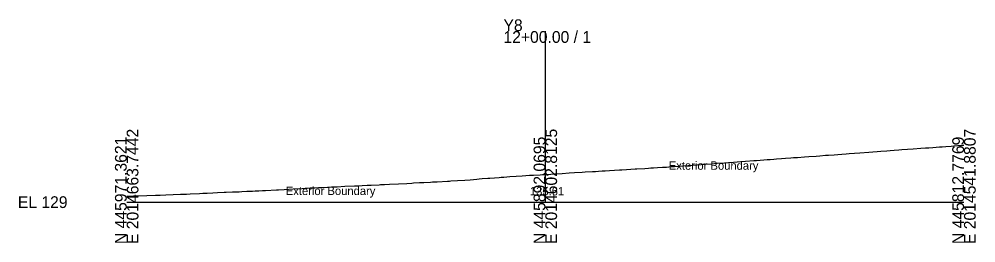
# Model space of a CAD drawing. Extents: x -26 to 1403, y -10 to 8043.
# Drawn here: x -25.7 to 202.8, y 3990.3 to 4043.6 of the extents above; entities that cross this region are included whole.
import ezdxf

# ---------------------------------------------------------------- set-up
doc = ezdxf.new("R2010")
doc.units = 0
for name, color, linetype in [('Default', 7, 'Continuous'), ('Exist Cross Section Cell', 7, 'Continuous'), ('Exist XS Center Line Elevation Label', 7, 'Continuous'), ('Exist XS Ground Line', 7, 'Continuous'), ('Scratch_Level_0', 7, 'Continuous')]:
    doc.layers.add(name, color=color, linetype=linetype)

msp = doc.modelspace()

# ---------------------------------------------------------------- linework, layer by layer
at = {"layer": 'Exist Cross Section Cell'}
for p, q in [((100, 4000), (100, 4040.76)), ((0, 4000), (100, 4000)), ((100, 4000), (200, 4000))]:
    msp.add_line(p, q, dxfattribs=at)
at = {"layer": 'Exist XS Ground Line'}
msp.add_lwpolyline([(0, 4001.44), (0.53, 4001.46), (1.66, 4001.49), (2.83, 4001.52), (4.78, 4001.58), (6.92, 4001.66), (7.98, 4001.69), (9.32, 4001.74), (11.09, 4001.81), (12.86, 4001.87), (14.27, 4001.94), (15.14, 4001.98), (17.41, 4002.08), (18.21, 4002.12), (19.24, 4002.17), (20.58, 4002.23), (21.72, 4002.28), (23.31, 4002.35), (23.78, 4002.37), (25.31, 4002.42), (26.87, 4002.49), (27.53, 4002.52), (28.68, 4002.58), (29.36, 4002.61), (30.04, 4002.64), (30.69, 4002.67), (31.57, 4002.72), (32.47, 4002.75), (33.13, 4002.78), (35.82, 4002.93), (36.29, 4002.95), (37.62, 4003), (39.75, 4003.16), (41.88, 4003.26), (42.62, 4003.32), (43.12, 4003.34), (43.79, 4003.38), (44.94, 4003.43), (45.78, 4003.47), (46.72, 4003.5), (47.94, 4003.58), (48.26, 4003.59), (48.95, 4003.63), (50.28, 4003.67), (52.12, 4003.79), (54.41, 4003.86), (55.26, 4003.91), (56.21, 4003.96), (57.42, 4004.01), (58.42, 4004.06), (60.29, 4004.16), (60.66, 4004.17), (61.56, 4004.21), (62.77, 4004.25), (64.9, 4004.39), (66.91, 4004.47), (68.12, 4004.55), (68.48, 4004.57), (69.93, 4004.65), (71, 4004.71), (72.56, 4004.78), (73.08, 4004.81), (74.15, 4004.86), (76.61, 4005.01), (77.07, 4005.03), (77.45, 4005.05), (79.03, 4005.13), (80.77, 4005.27), (82.03, 4005.35), (83.66, 4005.5), (84.18, 4005.54), (84.9, 4005.6), (86.27, 4005.71), (86.76, 4005.75), (88.97, 4005.91), (89.43, 4005.94), (90.1, 4005.99), (91.55, 4006.08), (93.06, 4006.19), (94.47, 4006.27), (96.2, 4006.39), (97.16, 4006.45), (98.75, 4006.54), (99.36, 4006.58), (100.2, 4006.62), (101.3, 4006.7), (101.87, 4006.73), (102.72, 4006.78), (104, 4006.85), (105.67, 4006.97), (106.93, 4007.04), (108.82, 4007.16), (109.54, 4007.21), (111.26, 4007.29), (111.97, 4007.34), (112.69, 4007.38), (113.61, 4007.44), (114.33, 4007.48), (115.32, 4007.54), (116.49, 4007.59), (117.68, 4007.68), (118.29, 4007.71), (119.35, 4007.76), (121.47, 4007.91), (121.87, 4007.93), (123.77, 4008.03), (124.65, 4008.1), (125.19, 4008.14), (125.85, 4008.18), (126.77, 4008.23), (127.98, 4008.31), (128.97, 4008.37), (130.08, 4008.46), (130.83, 4008.51), (131.81, 4008.58), (134.12, 4008.76), (136.27, 4008.9), (137.24, 4008.98), (137.65, 4009.02), (138.15, 4009.05), (139.73, 4009.16), (141.08, 4009.25), (142.79, 4009.38), (143.73, 4009.45), (144.92, 4009.54), (146.67, 4009.68), (147.79, 4009.75), (149.83, 4009.91), (150.47, 4009.96), (152.22, 4010.07), (152.99, 4010.13), (153.67, 4010.18), (154.57, 4010.25), (155.22, 4010.3), (156.41, 4010.38), (157.39, 4010.46), (158.68, 4010.55), (159.24, 4010.6), (160.21, 4010.67), (161.93, 4010.79), (162.93, 4010.86), (164.73, 4010.99), (165.59, 4011.06), (166.91, 4011.16), (167.64, 4011.21), (169.02, 4011.31), (169.85, 4011.37), (170.85, 4011.45), (171.85, 4011.52), (172.61, 4011.58), (175.12, 4011.77), (177.24, 4011.93), (178.2, 4012), (179.28, 4012.08), (180.13, 4012.15), (181.6, 4012.25), (182.37, 4012.31), (183.35, 4012.38), (184.4, 4012.45), (185.13, 4012.51), (187.83, 4012.7), (189.73, 4012.84), (190.83, 4012.92), (191.63, 4012.97), (192.59, 4013.05), (194.14, 4013.16), (194.83, 4013.21), (195.69, 4013.27), (196.93, 4013.36), (197.58, 4013.41), (199.42, 4013.54), (200, 4013.59)], dxfattribs=at)

# ---------------------------------------------------------------- texts
at = {"layer": 'Default'}
msp.add_text('-', height=0.0001, dxfattribs=at).set_placement((0, 4000))
at = {"layer": 'Exist Cross Section Cell'}
for s, p in [('Y8', (90, 4040.76)), ('12+00.00 / 1', (90, 4037.96)), ('EL 129', (-26, 3998.6))]:
    msp.add_text(s, height=2.8, dxfattribs=at).set_placement(p)
for s, p in [('N 445971.3621', (0, 3990)), ('E 2014663.7442', (2.8, 3990)), ('N 445892.0695', (100, 3990)), ('E 2014602.8125', (102.8, 3990)), ('N 445812.7769', (200, 3990)), ('E 2014541.8807', (202.8, 3990))]:
    msp.add_text(s, height=2.8, rotation=90, dxfattribs=at).set_placement(p)
at = {"layer": 'Exist XS Center Line Elevation Label'}
msp.add_text('135.61', height=2, dxfattribs=at).set_placement((96.32, 4001.61))
at = {"layer": 'Scratch_Level_0'}
for p in [(129.49, 4007.72), (38, 4001.69)]:
    msp.add_text('Exterior Boundary', height=2, dxfattribs=at).set_placement(p)

doc.saveas('drawing.dxf')
